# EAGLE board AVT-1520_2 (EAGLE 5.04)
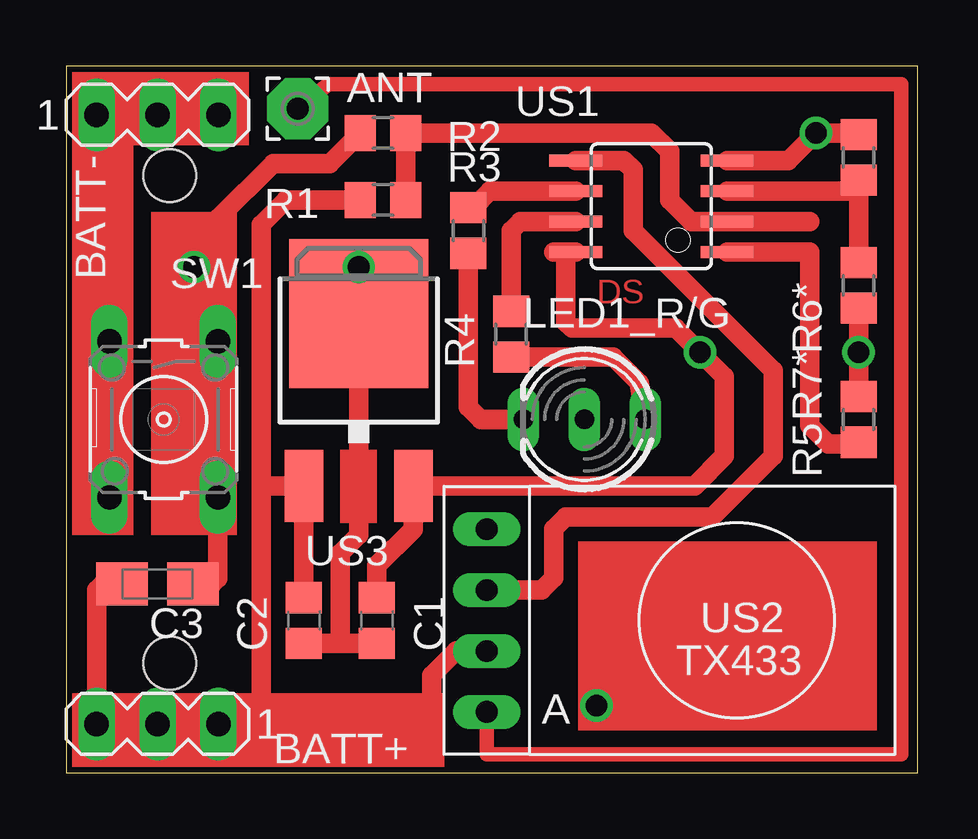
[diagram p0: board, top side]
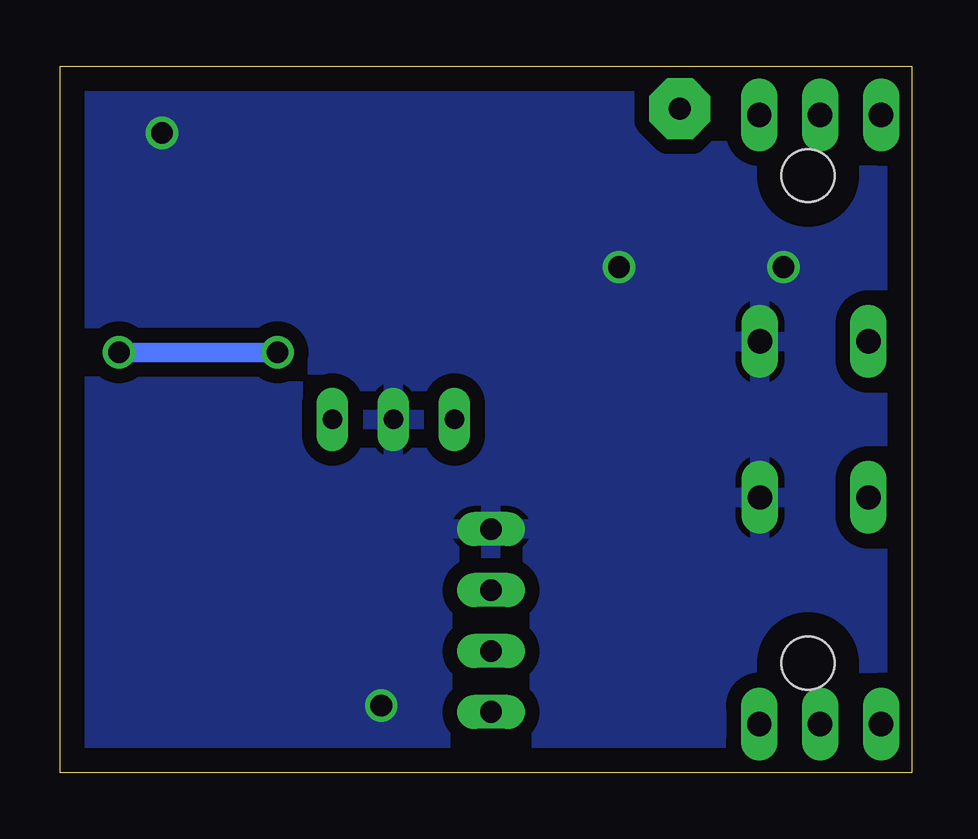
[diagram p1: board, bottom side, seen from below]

Size 35.48 x 29.45 mm. Coordinates in mm from the lower left corner, seen from the top.
Outline: 0,0 35.48,0 35.48,29.45 0,29.45 0,0
Copper layers (1*16): Top 0.035mm / dielectric 1.5mm / Bottom 0.035mm
Design rules "default": minimum track width 10mil, minimum drill 24mil, track to track 8mil, track to pad 8mil, pad to pad 8mil, via to via 8mil, smd to smd 8mil, copper to edge 40mil, drill to drill 8mil, minimum pad ring 10mil, minimum via ring 8mil, stop-mask expansion 4mil, vias tented up to drill 0mil, thermal gap 10mil
Holes 2.2 mm at 4.32,4.57 4.32,24.89

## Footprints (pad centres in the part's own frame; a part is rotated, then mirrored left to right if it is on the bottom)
2,54/0,9 = drill 0.914 pad 2.54 octagon: 1 0,0
MA03-1 = drill 1.016 long: 1 -2.54,0; 2 0,0; 3 2.54,0
C0805 = smd 1.3 x 1.5: 1 -0.95,0; 2 0.95,0
A/3216-18W = smd 2.15 x 1.8: + 1.475,0; - -1.475,0
DUOLED-C-5MM = drill 0.813 long: AR 2.54,0; AX -2.54,0; C 0,0
R0805 = smd 1.3 x 1.5: 1 -0.95,0; 2 0.95,0
B3F-10XX = drill 1.016 long: 1 -3.251,2.261; 2 3.251,2.261; 3 -3.251,-2.261; 4 3.251,-2.261
SOIC8 = smd 0.5 x 2.2: 1 -1.905,-3.154; 2 -0.645,-3.154; 3 0.625,-3.154; 4 1.895,-3.154; 5 1.905,3.154; 6 0.635,3.154; 7 -0.635,3.154; 8 -1.905,3.154
TX433 = drill 0.9 long: 1 -3.81,3.81; 2 -3.81,1.27; 3 -3.81,-1.27; 4 -3.81,-3.81
DPACK = smd 1.6 x 3: 1 -2.28,-4.8; 3 2.28,-4.8 | smd 5.8 x 6.2: 4 0,2.38

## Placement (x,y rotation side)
ANT  [2,54/0,9]  9.65,27.69 0 top
BATT+  CON1  [MA03-1]  3.81,2.03 180 top
BATT-  CON2  [MA03-1]  3.81,27.43 0 top
C1  100n  [C0805]  12.95,6.35 270 top
C2  100n  [C0805]  9.91,6.35 270 top
C3  10uF/16V  [A/3216-18W]  3.81,7.87 180 top
LED1_R/G  [DUOLED-C-5MM]  21.59,14.73 180 top
R1  10k  [R0805]  13.21,23.88 180 top
R2  1k  [R0805]  13.21,26.67 180 top
R3  1k  [R0805]  16.76,22.61 90 top
R4  1k  [R0805]  18.54,18.29 90 top
R5  10k  [R0805]  33.02,14.73 270 top
R6*  [R0805]  33.02,25.65 270 top
R7*  [R0805]  33.02,20.32 90 top
SW1  [B3F-10XX]  4.06,14.73 270 top
US1  ATTINY13  [SOIC8]  24.38,23.62 90 top
US2  TX433  [TX433]  21.34,6.35 0 top
US3  78L05  [DPACK]  12.19,16.76 0 top

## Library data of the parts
ANT = wirepad
BATT+ BATT- = con-lstb
C1-C3 R1-R5 R6* R7* = rcl
LED1_R/G = led
SW1 = switch-omron
US1 US2 = avr-4
US3 = v-reg

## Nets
+5V: C1.1 R5.1 R7*.1 US1.8 US3.3
GND: C1.2 C2.2 C3.- LED1_R/G.C R2.2 R6*.1 SW1.1 SW1.2 US1.4 US2.1 US3.4
N$1: US1.5 US2.2
N$2: R5.2 US1.1
N$3: ANT.1 US2.4
N$4: R1.1 R2.1 US1.2
N$5: LED1_R/G.AR R3.1
N$6: LED1_R/G.AX R4.1
N$7: R6*.2 R7*.2 US1.3
N$8: R4.2 US1.7
N$9: R3.2 US1.6
N$11: BATT-.1 BATT-.2 BATT-.3 SW1.3 SW1.4
VCC: BATT+.1 BATT+.2 BATT+.3 C2.1 C3.+ R1.2 US2.3 US3.1

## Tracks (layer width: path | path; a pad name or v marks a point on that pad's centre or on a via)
+5V  (via drill 0.9)
  Top 0.813: C1.1 12.95,8.64 14.47,10.15 US3.3 26.19,11.96 27.43,13.21 27.43,16.51 v26.42,17.53 25.4,18.54 21.08,18.54 20.83,18.8 20.83,21.46 20.57,21.72 | 20.57,21.72 US1.8 | 20.57,21.72 20.32,21.72 | R7*.1 v33.02,17.53 R5.1
  Bottom 0.813: v26.42,17.53 v33.02,17.53
GND  (via drill 0.9)
  Top 0.813: C3.- 6.1,7.87 6.33,8.1 SW1.2 SW1.1 6.35,18.01 6.35,21.08 | C2.2 11.43,5.4 | 11.43,5.4 C1.2 | 11.43,5.4 11.43,9.14 12.19,9.91 v12.19,21.08 US3.4 | 6.35,21.08 6.35,23.11 8.64,25.4 10.99,25.4 R2.2 | US1.4 30.09,25.52 v31.24,26.67 32.95,26.67 R6*.1 | 6.35,21.08 v5.33,21.08
  other vias: 22.1,2.79
  pour Bottom (isolate 0.61): 0.25,29.21 35.31,29.21 35.31,0.25 0.25,0.25
N$1
  Top 0.813: US1.5 23.24,25.53 23.62,25.15 23.62,22.61 29.46,16.76 29.46,13.21 26.92,10.67 20.83,10.67 20.32,10.16 20.32,8.13 19.81,7.62 US2.2
N$2
  Top 0.813: US1.1 30.99,21.72 30.99,14.48 31.75,13.72 32.95,13.72 R5.2
N$3
  Top 0.61: US2.4 17.53,0.76 34.8,0.76 34.8,28.7 10.92,28.7 ANT.1
N$4
  Top 0.813: R1.1 R2.1 24.38,26.67 25.15,25.91 25.15,23.88 26.05,22.98 US1.2
N$5
  Top 0.813: R3.1 16.76,15.24 17.27,14.73 LED1_R/G.AR
N$6
  Top 0.813: R4.1 22.79,17.34 23.88,16.26 LED1_R/G.AX
N$7
  Top 0.813: R7*.2 R6*.2 32.56,24.25 US1.3
N$8
  Top 0.813: US1.7 18.92,22.99 18.54,22.61 R4.2
N$9
  Top 0.813: US1.6 17.65,24.26 17.27,23.88 R3.2
N$10
  Top 0.813: 27.56,22.99 30.99,22.99
N$11
  Top 0.813: BATT-.3 BATT-.2 BATT-.1 1.27,18.52 SW1.3 SW1.4
N$16  (via drill 0.9)
  other vias: 26.42,17.53
VCC
  Top 0.813: 8.13,11.94 8.13,2.29 7.87,2.03 BATT+.1 | 8.13,11.94 8.15,11.96 US3.1 C2.1 | C3.+ 1.52,7.87 1.27,7.62 BATT+.3 BATT+.2 BATT+.1 | US2.3 16.26,5.08 15.24,4.06 15.24,2.03 BATT+.1 | R1.2 9.14,23.88 8.13,22.86 8.13,11.94
(copper drawn outside any net)
  shapes: Top area x6

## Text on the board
Top: DS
